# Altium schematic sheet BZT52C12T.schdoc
size 127 x 101 mm
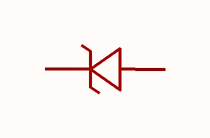
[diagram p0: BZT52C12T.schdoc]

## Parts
D?  bzt52c12t  [SOD-523_L1.2-W0.8-LS1.6-RD]  (value not drawn)

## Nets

Not connected (* = marked no-connect by the designer): D? 1(K) 2(A)

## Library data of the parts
D? = bzt52c12t: 二极管配置:1个独立式;稳压值(标称值):12V;稳压值(范围):11.4V~12.7V;耗散功率(Pd):200mW;; Manufacturer: MDD(辰达半导体); AddInBom: yes; ModelId: 8f56a03db567494d8f4c9d12aa52a741; ModelName: SOD-523_L1.2-W0.8-H0.7-LS1.6; ModelTransform: 62.992,31.496,0,180,0,0,0,0,0; Diode Configuration: 1个独立式; Zener Voltage(Nom): 12V; Reverse Leakage Current (Ir): 100nA@8V; Pd - Power Dissipation: 200mW; Impedance(Zzt): 25Ω; Impedance(Zzk): 150Ω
